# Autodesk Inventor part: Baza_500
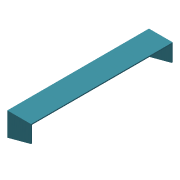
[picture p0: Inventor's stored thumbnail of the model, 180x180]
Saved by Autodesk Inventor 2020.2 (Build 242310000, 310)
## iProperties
Created: 2014-11
Part Number: Baza_500
Material: Ogólny
Document SubType Name: Modelowanie
Designer: F.Stasiak
Density: 1 g/cm^3
Appearance: Niebieska z odcieniem szarości
Sheet Metal Rule: Domyślny_mm
Catalog Web Link: www.expertbooks.pl
Manager: www.cadconsulting.pl
Company: Fabian Stasiak CAD Consulting
Author: F.Stasiak
Subject: Zbiór ćwiczeń. Autodesk Inventor 2020. Kurs Professional
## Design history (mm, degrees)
sketch "Szkic6"
  geometry: L1 (-220, 0)-(-220, -160); L2 (-220, -160)-(0, -218.949); L3 (-220, 0)-(0, 0); L4 (0, 0)-(0, -218.949)
  constraints: 8 end point, 2 vertical, 1 perpendicular
  dimensions: "d41" = 105 deg angle of L2 L1; "d42" = 220 distance of L1.start L3.end; "d43" = 160 distance of L1.start L1.end
extrude "Wyciągnięcie proste5" new body sketch "Szkic6" stored distance "d38" = 1312; taper "d39" = 0 deg
feature "Skorupa1" dims "d40" = 10
node "Bryła2"
other parameters: "WspółczynnikK" = 4.4, "GłębokośćGięciaPodcięcia" = 5 (= 0.5 x Grubość), "OdstępPołączenia" = 0.01
